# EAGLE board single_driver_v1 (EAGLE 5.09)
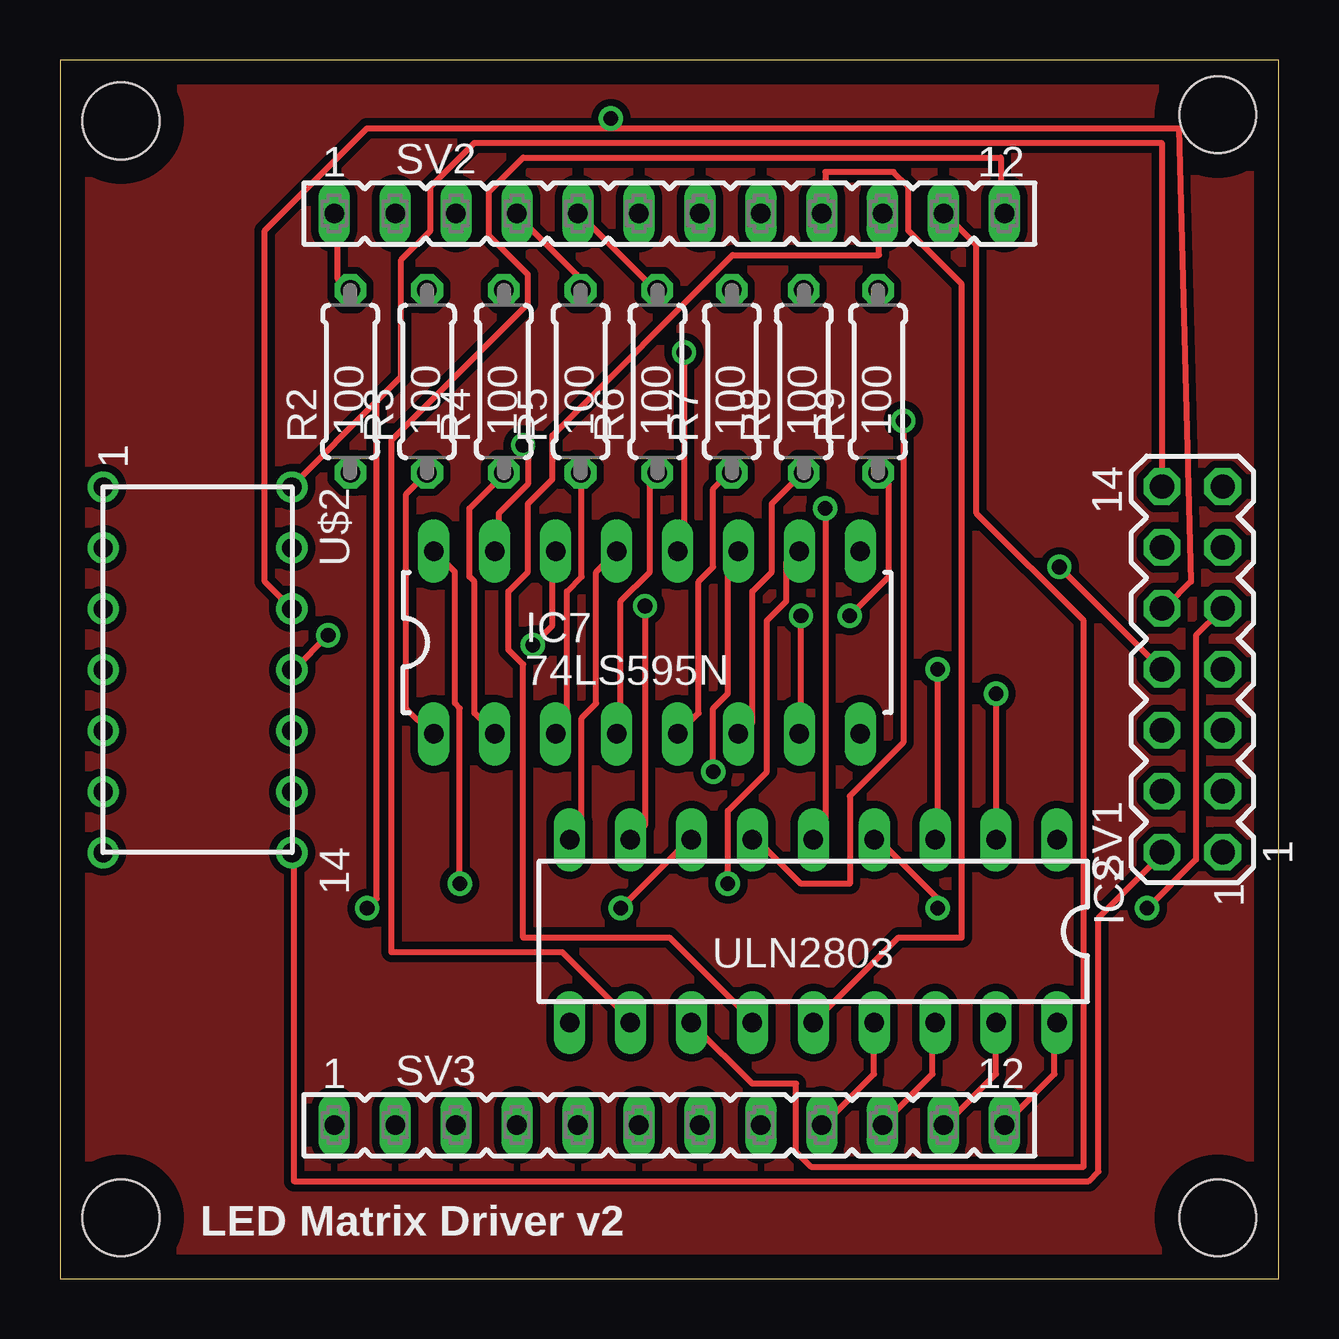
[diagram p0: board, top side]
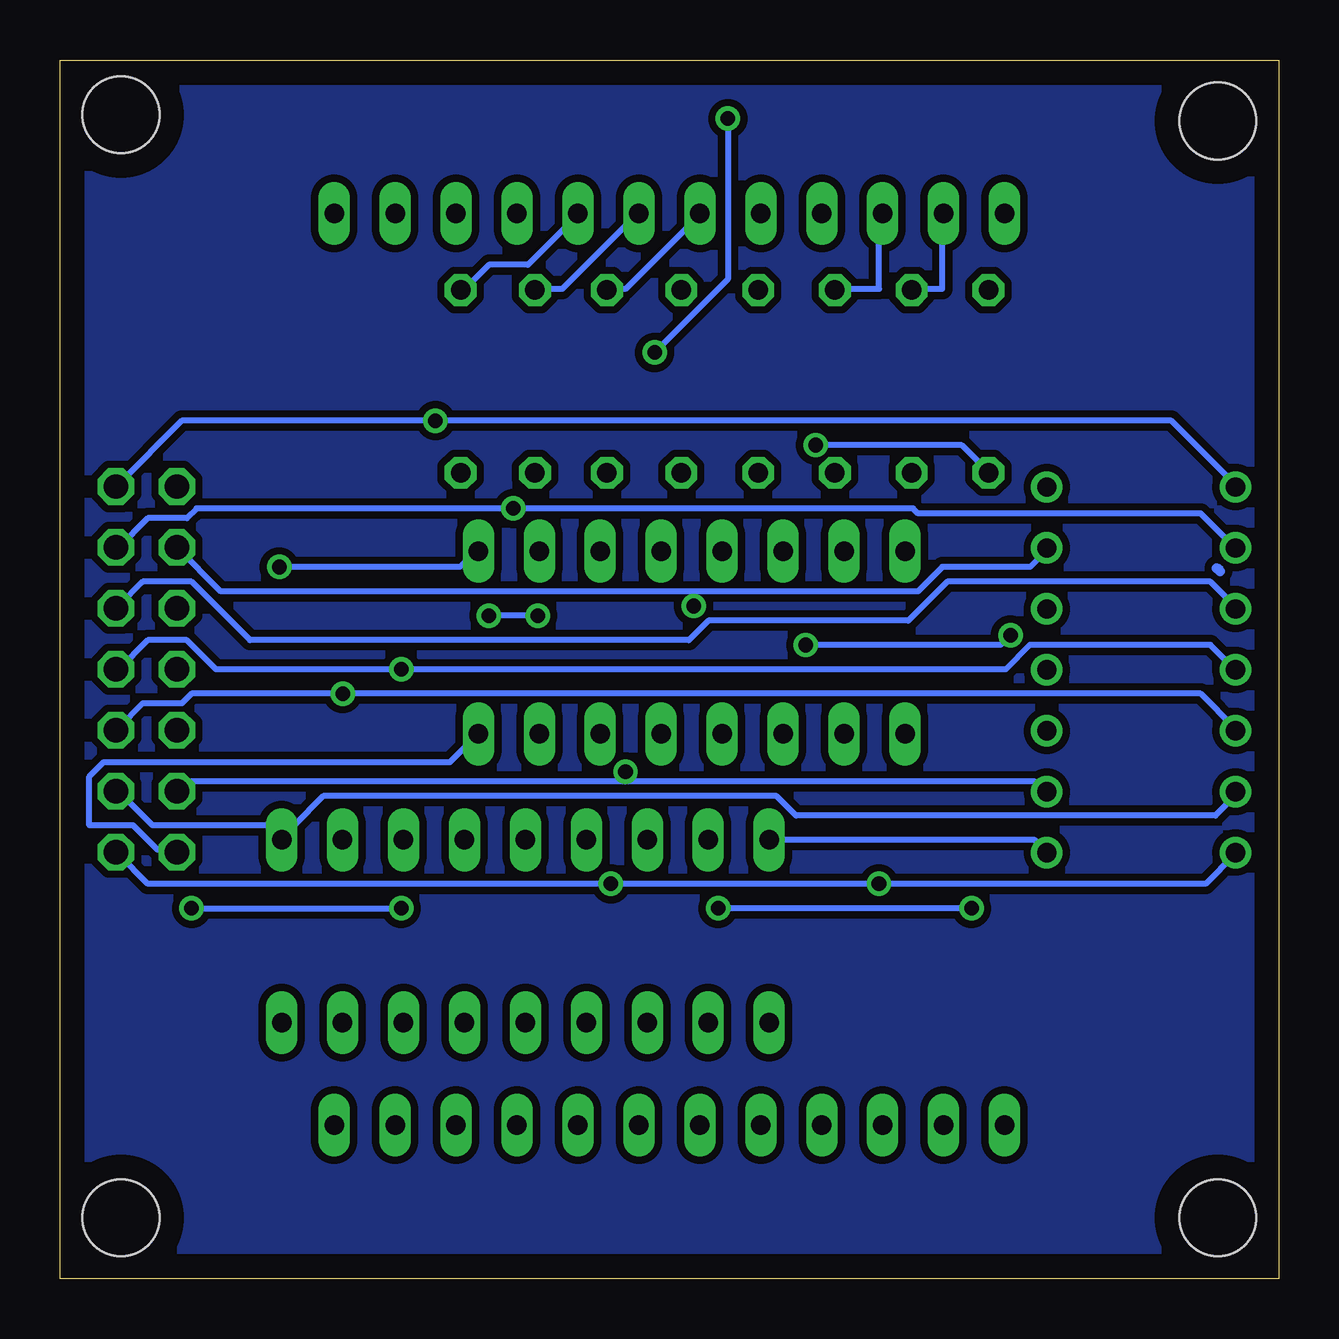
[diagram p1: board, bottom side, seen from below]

Size 50.8 x 50.8 mm. Coordinates in mm from the lower left corner, seen from the top.
Outline: 0,0 50.8,0 50.8,50.8 0,50.8 0,0
Copper layers (1*16): Top 0.035mm / dielectric 1.5mm / Bottom 0.035mm
Design rules "default": minimum track width 10mil, minimum drill 24mil, track to track 8mil, track to pad 8mil, pad to pad 8mil, via to via 8mil, smd to smd 8mil, copper to edge 40mil, drill to drill 8mil, minimum pad ring 10mil, minimum via ring 8mil, stop-mask expansion 4mil, vias tented up to drill 0mil, thermal gap 10mil
Holes 3.2 mm at 2.54,48.26 2.54,2.54 48.26,48.51 48.26,2.54

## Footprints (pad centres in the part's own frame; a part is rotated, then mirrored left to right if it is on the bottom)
DIL18 = drill 0.813 long: 1 -10.16,-3.81; 2 -7.62,-3.81; 3 -5.08,-3.81; 4 -2.54,-3.81; 5 0,-3.81; 6 2.54,-3.81; 7 5.08,-3.81; 8 7.62,-3.81; 9 10.16,-3.81; 10 10.16,3.81; 11 7.62,3.81; 12 5.08,3.81; 13 2.54,3.81; 14 0,3.81; 15 -2.54,3.81; 16 -5.08,3.81; 17 -7.62,3.81; 18 -10.16,3.81
DIL16 = drill 0.813 long: 1 -8.89,-3.81; 2 -6.35,-3.81; 3 -3.81,-3.81; 4 -1.27,-3.81; 5 1.27,-3.81; 6 3.81,-3.81; 7 6.35,-3.81; 8 8.89,-3.81; 9 8.89,3.81; 10 6.35,3.81; 11 3.81,3.81; 12 1.27,3.81; 13 -1.27,3.81; 14 -3.81,3.81; 15 -6.35,3.81; 16 -8.89,3.81
0207/7 = drill 0.813 octagon: 1 -3.81,0; 2 3.81,0
MA07-2 = drill 1.016 octagon: 1 -7.62,-1.27; 2 -7.62,1.27; 3 -5.08,-1.27; 4 -5.08,1.27; 5 -2.54,-1.27; 6 -2.54,1.27; 7 0,-1.27; 8 0,1.27; 9 2.54,-1.27; 10 2.54,1.27; 11 5.08,-1.27; 12 5.08,1.27; 13 7.62,-1.27; 14 7.62,1.27
FE12 = drill 0.813 long: 1 -13.97,0; 2 -11.43,0; 3 -8.89,0; 4 -6.35,0; 5 -3.81,0; 6 -1.27,0; 7 1.27,0; 8 3.81,0; 9 6.35,0; 10 8.89,0; 11 11.43,0; 12 13.97,0
F-7X2 = drill 0.8 round: 1 0,0; 2 0,7.87; 3 2.54,0; 4 2.54,7.87; 5 5.08,0; 6 5.08,7.87; 7 7.62,0; 8 7.62,7.87; 9 10.16,0; 10 10.16,7.87; 11 12.7,0; 12 12.7,7.87; 13 15.24,0; 14 15.24,7.87

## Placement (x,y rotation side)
IC2  [DIL18]  31.4,14.48 180 top
IC7  74LS595N  [DIL16]  24.47,26.52 0 top
R2  100  [0207/7]  12.1,37.4 90 top
R3  100  [0207/7]  15.3,37.4 90 top
R4  100  [0207/7]  18.5,37.4 90 top
R5  100  [0207/7]  21.7,37.4 90 top
R6  100  [0207/7]  24.9,37.4 90 top
R7  100  [0207/7]  28,37.4 90 top
R8  100  [0207/7]  31,37.4 90 top
R9  100  [0207/7]  34.1,37.4 90 top
SV1  OUT  [MA07-2]  47.2,25.4 90 top
SV2  [FE12]  25.4,44.4 0 top
SV3  [FE12]  25.4,6.4 0 top
U$2  F_HEADER_CUST  [F-7X2]  1.8,33 270 top

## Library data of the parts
IC2 = uln-udn
IC7 = SparkFun
R2-R9 = resistor
SV1 = con-lstb
SV2 SV3 = con-lsta
U$2 = headers

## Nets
5V: IC7.10 IC7.16 SV1.1 U$2.13
B0: IC2.1 SV1.3 U$2.11
B1: IC2.2 SV1.5 U$2.9
B2: IC2.3 SV1.7 U$2.7
B3: IC2.4 SV1.9 U$2.5
B4: IC2.5 SV1.11 U$2.3
B5: IC2.6 SV1.13 U$2.1
B6: IC2.7 SV1.14 U$2.2
B7: IC2.8 SV1.12 U$2.4
GND: IC2.9 IC7.8 IC7.13 SV1.2 U$2.14
N: IC7.14 U$2.8
N$4: IC2.11 SV2.12
N$6: IC2.12 SV2.11
N$7: IC2.13 SV2.10
N$8: IC7.15 R2.1
N$9: IC2.14 SV2.9
N$10: IC2.18 SV3.12
N$11: IC7.1 R3.1
N$12: IC7.2 R4.1
N$13: IC7.3 R5.1
N$14: IC7.4 R6.1
N$15: IC7.5 R7.1
N$16: IC7.6 R8.1
N$17: IC7.7 R9.1
N$18: R2.2 SV2.1
N$19: R3.2 SV2.2
N$20: R4.2 SV2.3
N$21: R5.2 SV2.4
N$22: R6.2 SV2.5
N$23: R7.2 SV2.6
N$24: R8.2 SV2.7
N$25: R9.2 SV2.8
N$26: IC2.17 SV3.11
N$27: IC2.16 SV3.10
N$28: IC2.15 SV3.9
SCK: IC7.11 SV1.4 U$2.12
SER: IC7.9 SV1.8
SS: IC7.12 SV1.10 U$2.6

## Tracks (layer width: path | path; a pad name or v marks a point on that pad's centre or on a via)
5V  (via drill 0.61)
  Top 0.254: v16.66,16.46 16.66,23.77 16.46,23.98 16.46,29.46 15.65,30.28 IC7.16 | v27.84,16.46 27.84,19.51 29.46,21.13 29.46,27.43 30.28,28.25 30.28,29.87 30.68,30.28 IC7.10
  Bottom 0.254: U$2.13 1.83,17.68 3.05,16.46 v16.66,16.46 v27.84,16.46 47.14,16.46 48.36,17.68 SV1.1
B0
  Bottom 0.254: 41.05,18.9 41.45,18.49 IC2.1 41.05,18.9 | 41.05,18.9 39.83,20.12 20.93,20.12 20.12,19.3 2.64,19.3 1.83,20.12 U$2.11 | 41.05,18.9 46.94,18.9 48.36,20.32 SV1.3
B1  (via drill 0.61)
  Top 0.254: v39.01,24.38 39.01,18.49 IC2.2
  Bottom 0.254: U$2.9 1.83,22.96 3.25,24.38 v39.01,24.38 45.31,24.38 45.72,23.98 47.35,23.98 48.36,22.96 SV1.5
B2  (via drill 0.61)
  Top 0.254: v36.58,25.4 36.58,18.49 IC2.3
  Bottom 0.254: U$2.7 1.83,25.4 2.85,26.42 10.36,26.42 11.38,25.4 v36.58,25.4 44.3,25.4 45.52,26.62 47.14,26.62 48.36,25.4 SV1.7
B3  (via drill 0.61)
  Top 0.254: v36.58,15.44 36.58,15.85 34.14,18.29 IC2.4 | v45.31,15.44 47.35,17.48 47.35,26.82 48.36,27.84 SV1.9
  Bottom 0.254: U$2.5 1.83,28.04 2.85,29.06 13.82,29.06 15.44,27.43 23.77,27.43 24.59,26.62 42.88,26.62 45.31,29.06 47.35,29.06 48.36,28.04 SV1.9 | v45.31,15.44 v36.58,15.44
B4  (via drill 0.61)
  Top 0.254: v31.9,32.11 31.9,18.9 31.5,18.49 IC2.5
  Bottom 0.254: U$2.3 1.83,30.48 3.25,31.9 15.04,31.9 15.24,32.11 v31.9,32.11 45.11,32.11 45.52,31.7 47.14,31.7 48.36,30.48 SV1.11
B5  (via drill 0.61)
  Top 0.254: v35.15,35.76 35.15,22.35 32.92,20.12 32.92,16.46 30.89,16.46 29.06,18.29 IC2.6
  Bottom 0.254: U$2.1 1.83,33.12 4.47,35.76 v35.15,35.76 45.72,35.76 48.36,33.12 SV1.13
B6  (via drill 0.61)
  Top 0.254: 13.21,36.58 14.22,37.59 14.22,42.47 15.44,43.69 15.44,45.52 17.27,47.35 45.92,47.35 45.92,33.12 SV1.14 | 13.21,36.58 9.75,33.12 U$2.2 | v23.37,15.44 26.21,18.29 IC2.7 | v12.8,15.44 13.21,15.85 13.21,36.58
  Bottom 0.254: v12.8,15.44 v23.37,15.44
B7  (via drill 0.61)
  Top 0.254: v24.38,28.04 24.38,18.9 23.98,18.49 IC2.8
  Bottom 0.254: 24.38,28.65 44.09,28.65 SV1.12 | 24.38,28.65 15.04,28.65 14.02,29.67 10.36,29.67 9.75,30.28 U$2.4 | 24.38,28.65 v24.38,28.04
GND
  Top 0.254: IC7.13 23.16,30.28 22.35,29.46 22.35,23.98 21.74,23.37 21.74,18.9 21.34,18.49 IC2.9 | SV1.2 45.92,17.68 43.28,15.04 43.28,4.47 42.88,4.06 9.75,4.06 9.75,17.68 U$2.14
  Bottom 0.254: IC7.8 33.53,22.55 34.54,21.54 48.97,21.54 49.58,20.93 49.58,18.9 47.75,18.9 46.74,17.88 46.13,17.88 SV1.2 | U$2.14 9.75,17.88 10.16,18.29 21.13,18.29 IC2.9
N  (via drill 0.61)
  Top 0.254: v11.18,26.82 9.75,25.4 U$2.8 | v19.71,26.42 20.52,27.23 20.52,30.28 IC7.14
  Bottom 0.254: v11.18,26.82 11.58,26.42 v19.71,26.42
N$1
  pour Top (isolate 0.305): 0,50.8 50.8,50.8 50.8,0 0,0
N$2
  pour Bottom (isolate 0.305): 0,50.8 50.8,50.8 50.8,0 0,0
N$3
  Bottom 0.406: 2.44,29.49 2.59,29.62
N$4
  Top 0.254: IC2.11 23.77,10.77 20.93,13.61 13.82,13.61 13.82,34.95 19.51,40.64 19.51,41.86 17.88,43.48 17.88,45.31 19.3,46.74 39.22,46.74 39.22,44.5 SV2.12
N$6
  Top 0.254: IC2.12 26.42,10.57 28.85,8.13 30.68,8.13 30.68,5.28 31.29,4.67 42.67,4.67 42.67,27.43 38.2,31.9 38.2,43.08 36.98,44.3 SV2.11
N$7
  Top 0.254: IC2.13 28.85,10.77 25.4,14.22 19.3,14.22 19.3,25.6 18.69,26.21 18.69,28.65 19.51,29.46 19.51,32.31 20.52,33.33 20.52,35.15 28.04,42.67 34.14,42.67 34.14,44.3 SV2.10
N$8  (via drill 0.61)
  Top 0.254: v19.3,34.75 19.51,34.54 19.51,33.12 18.29,31.9 18.29,30.48 IC7.15
  Bottom 0.254: v19.3,34.75 13.21,34.75 12.19,33.73 R2.1
N$9
  Top 0.254: IC2.14 31.5,10.77 34.95,14.22 37.59,14.22 37.59,41.45 35.36,43.69 35.36,45.52 34.75,46.13 31.9,46.13 31.9,44.5 SV2.9
N$10
  Top 0.254: SV3.12 39.42,6.5 41.45,8.53 41.45,10.57 IC2.18
N$11
  Top 0.254: IC7.1 15.44,22.76 14.43,23.77 14.43,32.72 15.24,33.53 R3.1
N$12
  Top 0.254: IC7.2 18.09,22.76 17.27,23.57 17.27,29.06 17.07,29.26 17.07,32.11 18.49,33.53 R4.1
N$13
  Top 0.254: IC7.3 20.73,22.76 21.13,23.16 21.13,28.65 21.74,29.26 21.74,33.53 R5.1
N$14
  Top 0.254: IC7.4 23.37,22.76 23.37,28.25 24.59,29.46 24.59,33.33 24.79,33.53 R6.1
N$15
  Top 0.254: IC7.5 25.81,22.76 26.62,23.57 26.62,29.06 27.23,29.67 27.23,32.92 27.84,33.53 R7.1
N$16
  Top 0.254: IC7.6 28.45,22.76 28.85,23.16 28.85,28.65 29.67,29.46 29.67,32.31 30.89,33.53 R8.1
N$17  (via drill 0.61)
  Top 0.254: v30.89,27.64 30.89,22.76 IC7.7 | v32.92,27.64 34.54,29.26 34.54,33.12 34.14,33.53 R9.1
  Bottom 0.254: v30.89,27.64 v32.92,27.64
N$18
  Top 0.254: R2.2 11.99,41.25 11.58,41.66 11.58,44.3 SV2.1
N$19
  Bottom 0.254: SV2.2 14.02,44.3 14.02,41.25 15.24,41.25 R3.2
N$20
  Bottom 0.254: SV2.3 16.66,44.3 16.66,41.25 18.49,41.25 R4.2
N$21
  Top 0.254: SV2.4 19.1,44.3 21.54,41.86 21.54,41.25 R5.2
N$22
  Top 0.254: SV2.5 21.74,44.3 24.79,41.25 R6.2
N$23
  Bottom 0.254: SV2.6 24.18,44.3 27.23,41.25 27.84,41.25 R7.2
N$24
  Bottom 0.254: SV2.7 26.82,44.3 29.87,41.25 30.89,41.25 R8.2
N$25
  Bottom 0.254: SV2.8 29.26,44.3 31.29,42.27 32.92,42.27 33.93,41.25 R9.2
N$26
  Top 0.254: SV3.11 36.98,6.5 39.01,8.53 39.01,10.57 IC2.17
N$27
  Top 0.254: SV3.10 34.34,6.5 36.37,8.53 36.37,10.57 IC2.16
N$28
  Top 0.254: SV3.9 31.9,6.5 33.93,8.53 33.93,10.57 IC2.15
SCK  (via drill 0.61)
  Top 0.254: v27.23,21.13 27.23,23.77 27.84,24.38 27.84,29.87 28.25,30.28 IC7.11
  Bottom 0.254: 27.23,20.73 45.52,20.73 SV1.4 | 27.23,20.73 10.16,20.73 9.75,20.32 U$2.12 | 27.23,20.73 v27.23,21.13
SER  (via drill 0.61)
  Top 0.254: v41.66,29.67 SV1.8
  Bottom 0.254: v41.66,29.67 34.14,29.67 33.53,30.28 IC7.9
SS  (via drill 0.61)
  Top 0.254: 22.96,47.95 46.63,47.95 47.14,29.06 46.13,28.04 SV1.10 | 22.96,47.95 12.8,47.95 8.53,43.69 8.53,29.06 9.55,28.04 U$2.6 | v26.01,38.61 26.01,30.68 25.81,30.48 IC7.12 | 22.96,47.95 v22.96,48.36
  Bottom 0.254: v26.01,38.61 22.96,41.66 v22.96,48.36

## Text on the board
_tsilk: 1 | 100 | 100 | 100 | 100 | 100 | 100 | 100 | 100 | 14 | 74LS595N | 14 | 1 | ULN2803 | LED Matrix Driver v2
